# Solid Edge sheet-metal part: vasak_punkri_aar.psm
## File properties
Author: Blackblade
Template: Normal.psm
Last saved by: Blackblade
Revision: 3
Application: Solid Edge
Accuracy: 0.990
Material Thickness: 1.00 mm
Bend Radius: 1.00 mm
Relief Width: 1.00 mm
Relief Length: 0.00 mm
Neutral Factor: 0.330
Minimum Arc Length: 0.10 mm
Deviational Tolerance: 0.10 mm
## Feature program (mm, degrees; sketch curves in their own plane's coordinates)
base tab "unnamed BaseTab 1"
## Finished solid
Body 1: solid body, 4 faces, 6 edges, 4 vertices.
  Faces by surface: plane 3, cylinder 1
  Edges by curve: line 4, circle 2
Bounding box of the edges (mm): 170.000 x 14.464 x 1.000, from (-68.3271, 57.0007, 0) to (101.6729, 71.4645, 1).
Cylindrical faces by radius (mm): R649 x1
Planar faces by outward normal: +z 1, -z 1, oblique 1
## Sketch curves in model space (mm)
arc centre (67.9255, 576.7191, 0) radius 649 from (-68.3271, -57.8171, 0) through (16.2247, -70.2183, 0) to (101.6729, -71.4029, 0)
line (-68.3271, -57.8171, 0) -> (101.6729, -71.4029, 0)
arc centre (67.9255, -577.5355, 0) radius 649 from (-68.3271, 57.0007, 0) through (16.2247, 69.4019, 0) to (101.6729, 70.5865, 0)
line (101.6729, 70.5865, 0) -> (-68.3271, 57.0007, 0)
arc centre (67.9255, 576.7191, 0) radius 649 from (-116.258, -45.5971, 0) through (128.625, -69.4361, 0) to (364.7842, -0.4082, 0)
arc centre (-50.426, -0.4082, 0) radius 79.8492 from (-130.2752, -0.4082, 0) through (-126.6904, -24.0647, 0) to (-116.258, -45.5971, 0)
arc centre (-50.426, -0.4082, 0) radius 79.8492 from (-130.2752, -0.4082, 0) through (-126.6904, 23.2483, 0) to (-116.258, 44.7807, 0)
arc centre (67.9255, -577.5355, 0) radius 649 from (-116.258, 44.7807, 0) through (128.625, 68.6197, 0) to (364.7842, -0.4082, 0)
arc centre (67.9255, -577.5355, 0) radius 649 from (-68.3271, 57.0007, 0) through (-92.6009, 51.2986, 0) to (-116.6378, 44.6682, 0)
arc centre (-50.426, -0.4082, 0) radius 80.0992 from (-116.6378, -45.4846, 0) through (-130.5252, -0.4082, 0) to (-116.6378, 44.6682, 0)
arc centre (67.9255, 576.7191, 0) radius 649 from (-116.6378, -45.4846, 0) through (-92.6009, -52.115, 0) to (-68.3271, -57.8171, 0)
line (-68.3271, -57.8171, 0) -> (-68.3271, 57.0007, 0)
line (101.6729, -71.4029, 0) -> (101.6729, 70.5865, 0)
arc centre (67.9255, 576.7191, 0) radius 649 from (101.6729, -71.4029, 0) through (236.9969, -49.8715, 0) to (364.7842, -0.4082, 0)
arc centre (67.9255, -577.5355, 0) radius 649 from (364.7842, -0.4082, 0) through (236.9969, 49.0552, 0) to (101.6729, 70.5865, 0)
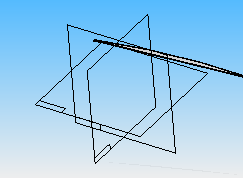
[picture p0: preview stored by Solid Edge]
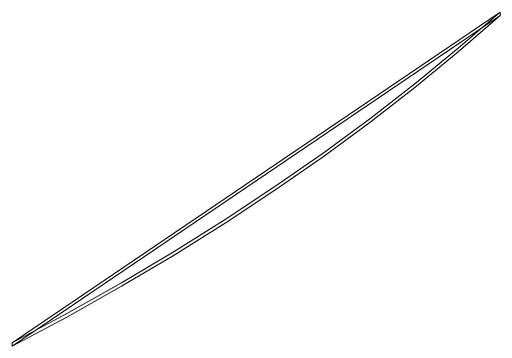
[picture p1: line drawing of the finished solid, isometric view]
